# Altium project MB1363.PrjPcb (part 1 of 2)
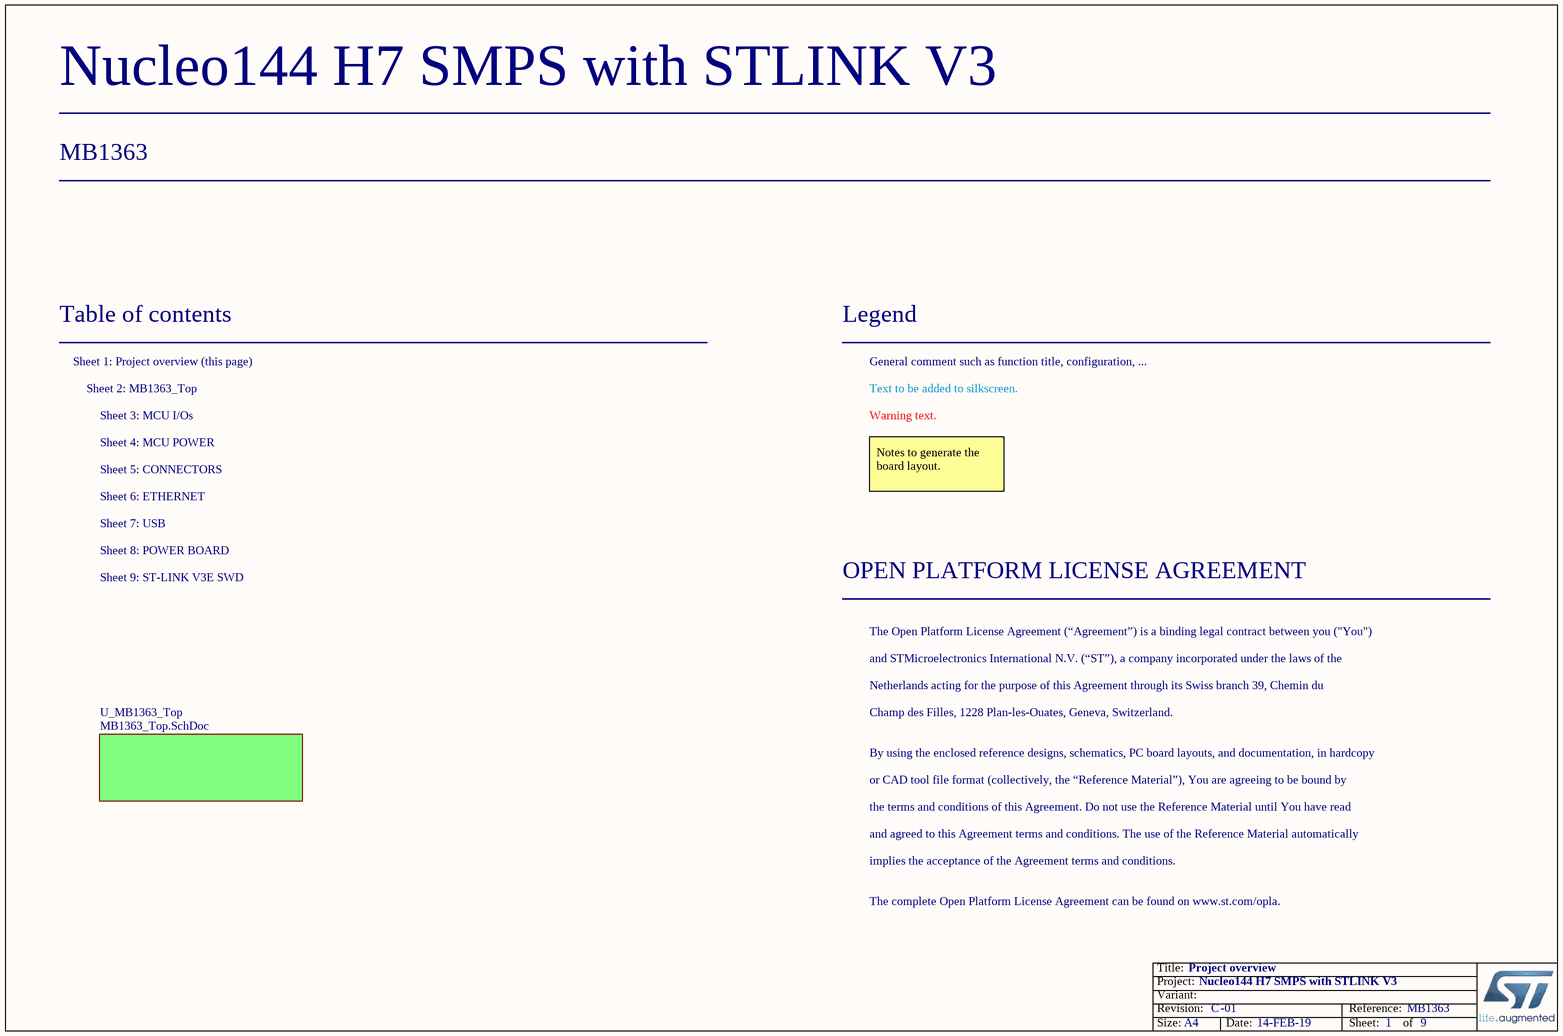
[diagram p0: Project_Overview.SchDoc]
Board_Reference: MB1363; Board_PCB_Revision: C; Board_Name: Nucleo144 H7 SMPS with STLINK V3; Board_Document_Date: 14-FEB-19; Board_Assembly_Revision: 01
9 sheets, 364 parts. Net scope: flat (ports and power ports of the same name join across sheets).
Board file: MB1363.PcbDoc
Sheets:
  Project_Overview.SchDoc
    U_MB1363_Top = mb1363_Top.SchDoc
      U_Connectors = Connectors.SchDoc
      U_Power_Board = Power_Board.SchDoc
      U_MCU_144_IOs = MCU_144_IOs.SchDoc
      U_MCU_144_POWER = MCU_144_POWER.SchDoc
      U_USB = USB.SchDoc
      U_Ethernet = Ethernet.SchDoc
      U_ST_LINK_V3E = ST_LINK_V3E.SchDoc

## Sheet Project_Overview.SchDoc: Project overview
size A4; Date: Not used; ApprovedBy: Not used; CheckedBy: Not used; Author: Not used; CompanyName: STMicroelectronics; DrawnBy: Not used; Engineer: Not used; Organization: Not used; Address1: Not used; Address2: Not used; Address3: Not used; Address4: Not used; DocumentNumber: 1; Revision: Not used; SheetNumber: 1; SheetTotal: 9

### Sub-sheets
U_MB1363_Top = MB1363_Top.SchDoc: no entries

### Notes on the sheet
- Table of contents
- Sheet 1: Project overview (this page)
- Legend
- General comment such as function title, configuration, ...
- Sheet 2: MB1363_Top
- Sheet 4: MCU POWER
- Sheet 3: MCU I/Os
- Text to be added to silkscreen.
- Warning text.
- Sheet 6: ETHERNET
- Sheet 5: CONNECTORS
- Notes to generate the board layout.
- Sheet 9: ST-LINK V3E SWD
- Sheet 7: USB
- Sheet 8: POWER BOARD
- OPEN PLATFORM LICENSE AGREEMENT
- The Open Platform License Agreement (“Agreement”) is a binding legal contract between you ("You")
- and STMicroelectronics International N.V. (“ST”), a company incorporated under the laws of the
- Netherlands acting for the purpose of this Agreement through its Swiss branch 39, Chemin du
- Champ des Filles, 1228 Plan-les-Ouates, Geneva, Switzerland.
- By using the enclosed reference designs, schematics, PC board layouts, and documentation, in hardcopy
- or CAD tool file format (collectively, the “Reference Material”), You are agreeing to be bound by
- the terms and conditions of this Agreement. Do not use the Reference Material until You have read
- and agreed to this Agreement terms and conditions. The use of the Reference Material automatically
- implies the acceptance of the Agreement terms and conditions.
- The complete Open Platform License Agreement can be found on www.st.com/opla.

## Sheet mb1363_Top.SchDoc: MB1363 Top: hierarchical view
size A4; Date: Not used; ApprovedBy: Not used; CheckedBy: Not used; Author: Not used; CompanyName: STMicroelectronics; DrawnBy: Not used; Engineer: Not used; Organization: Not used; Address1: Not used; Address2: Not used; Address3: Not used; Address4: Not used; DocumentNumber: 2; Revision: Not used; SheetNumber: 2; SheetTotal: 9
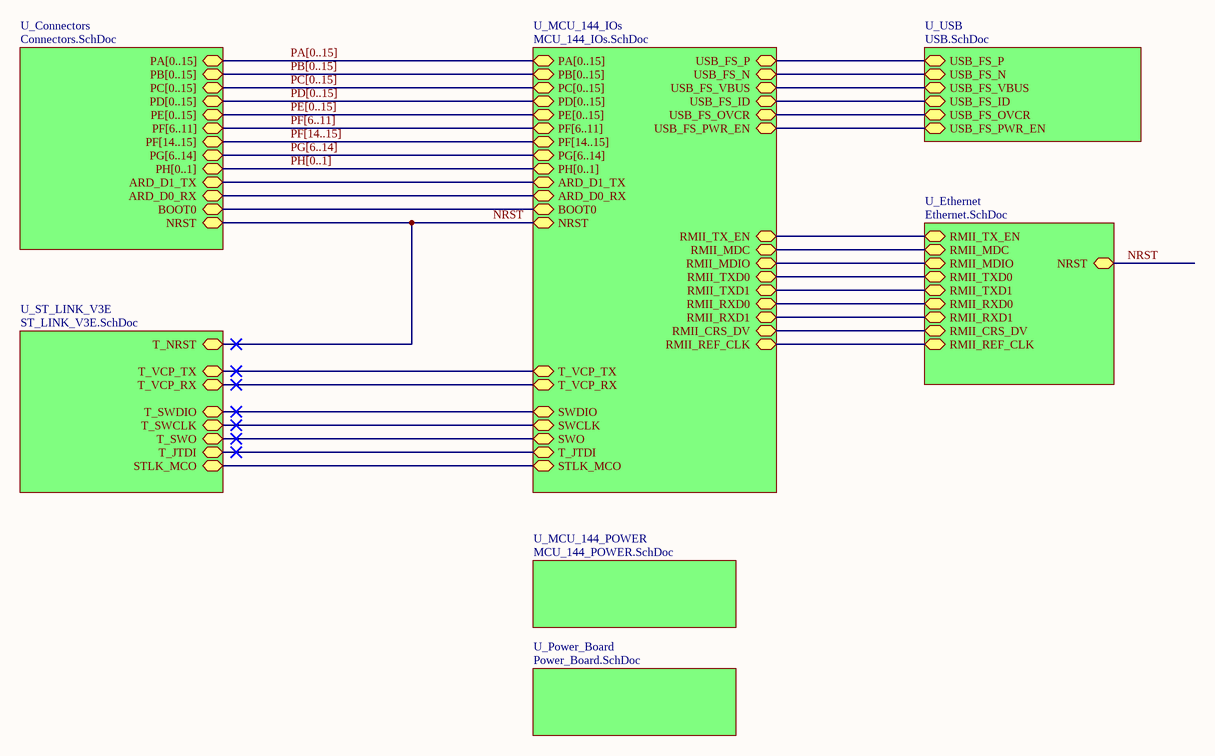
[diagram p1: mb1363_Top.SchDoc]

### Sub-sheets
U_Connectors = Connectors.SchDoc: PA[0..15] (bidir), PB[0..15] (bidir), PC[0..15] (bidir), NRST (bidir), PD[0..15] (bidir), PE[0..15] (bidir), PF[6..11] (bidir), PG[6..14] (bidir), PH[0..1] (bidir), BOOT0 (bidir), PF[14..15] (bidir), ARD_D1_TX (bidir), ARD_D0_RX (bidir)
U_Ethernet = Ethernet.SchDoc: RMII_CRS_DV (bidir), RMII_REF_CLK (bidir), RMII_TXD0 (bidir), RMII_RXD0 (bidir), RMII_TX_EN (bidir), NRST (bidir), RMII_RXD1 (bidir), RMII_MDC (bidir), RMII_TXD1 (bidir), RMII_MDIO (bidir)
U_MCU_144_IOs = MCU_144_IOs.SchDoc: NRST (bidir), BOOT0 (bidir), SWO (bidir), STLK_MCO (bidir), SWCLK (bidir), SWDIO (bidir), RMII_TX_EN (bidir), RMII_MDC (bidir), RMII_TXD0 (bidir), RMII_TXD1 (bidir), RMII_REF_CLK (bidir), RMII_RXD1 (bidir), RMII_MDIO (bidir), RMII_CRS_DV (bidir), RMII_RXD0 (bidir), USB_FS_N (bidir), USB_FS_P (bidir), USB_FS_OVCR (bidir), USB_FS_PWR_EN (bidir), USB_FS_VBUS (bidir), USB_FS_ID (bidir), T_VCP_TX (bidir), T_VCP_RX (bidir), PA[0..15] (bidir), PB[0..15] (bidir), PC[0..15] (bidir), PD[0..15] (bidir), PE[0..15] (bidir), PF[6..11] (bidir), PG[6..14] (bidir), PH[0..1] (bidir), PF[14..15] (bidir), ARD_D1_TX (bidir), ARD_D0_RX (bidir), T_JTDI (bidir)
U_MCU_144_POWER = MCU_144_POWER.SchDoc: no entries
U_Power_Board = Power_Board.SchDoc: no entries
U_ST_LINK_V3E = ST_LINK_V3E.SchDoc: T_NRST (bidir), STLK_MCO (bidir), T_SWDIO (bidir), T_VCP_TX (bidir), T_VCP_RX (bidir), T_SWCLK (bidir), T_SWO (bidir), T_JTDI (bidir)
U_USB = USB.SchDoc: USB_FS_N (bidir), USB_FS_P (bidir), USB_FS_OVCR (bidir), USB_FS_PWR_EN (bidir), USB_FS_VBUS (bidir), USB_FS_ID (bidir)

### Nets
NRST: sheet U_Connectors/NRST, sheet U_MCU_144_IOs/NRST, sheet U_Ethernet/NRST, sheet U_ST_LINK_V3E/T_NRST
(unnamed): sheet U_Connectors/BOOT0, sheet U_MCU_144_IOs/BOOT0
(unnamed): sheet U_Connectors/ARD_D1_TX, sheet U_MCU_144_IOs/ARD_D1_TX  [a separate net that carries the same name]
(unnamed): sheet U_Connectors/ARD_D0_RX, sheet U_MCU_144_IOs/ARD_D0_RX  [a separate net that carries the same name]
(unnamed): sheet U_MCU_144_IOs/SWO, sheet U_ST_LINK_V3E/T_SWO  [a separate net that carries the same name]
(unnamed): sheet U_MCU_144_IOs/STLK_MCO, sheet U_ST_LINK_V3E/STLK_MCO  [a separate net that carries the same name]
(unnamed): sheet U_MCU_144_IOs/SWCLK, sheet U_ST_LINK_V3E/T_SWCLK  [a separate net that carries the same name]
(unnamed): sheet U_MCU_144_IOs/SWDIO, sheet U_ST_LINK_V3E/T_SWDIO  [a separate net that carries the same name]
(unnamed): sheet U_MCU_144_IOs/RMII_TX_EN, sheet U_Ethernet/RMII_TX_EN  [a separate net that carries the same name]
(unnamed): sheet U_MCU_144_IOs/RMII_MDC, sheet U_Ethernet/RMII_MDC  [a separate net that carries the same name]
(unnamed): sheet U_MCU_144_IOs/RMII_TXD0, sheet U_Ethernet/RMII_TXD0  [a separate net that carries the same name]
(unnamed): sheet U_MCU_144_IOs/RMII_TXD1, sheet U_Ethernet/RMII_TXD1  [a separate net that carries the same name]
(unnamed): sheet U_MCU_144_IOs/RMII_REF_CLK, sheet U_Ethernet/RMII_REF_CLK  [a separate net that carries the same name]
(unnamed): sheet U_MCU_144_IOs/RMII_RXD1, sheet U_Ethernet/RMII_RXD1  [a separate net that carries the same name]
(unnamed): sheet U_MCU_144_IOs/RMII_MDIO, sheet U_Ethernet/RMII_MDIO  [a separate net that carries the same name]
(unnamed): sheet U_MCU_144_IOs/RMII_CRS_DV, sheet U_Ethernet/RMII_CRS_DV  [a separate net that carries the same name]
(unnamed): sheet U_MCU_144_IOs/RMII_RXD0, sheet U_Ethernet/RMII_RXD0  [a separate net that carries the same name]
(unnamed): sheet U_MCU_144_IOs/USB_FS_N, sheet U_USB/USB_FS_N  [a separate net that carries the same name]
(unnamed): sheet U_MCU_144_IOs/USB_FS_P, sheet U_USB/USB_FS_P  [a separate net that carries the same name]
(unnamed): sheet U_MCU_144_IOs/USB_FS_OVCR, sheet U_USB/USB_FS_OVCR  [a separate net that carries the same name]
(unnamed): sheet U_MCU_144_IOs/USB_FS_PWR_EN, sheet U_USB/USB_FS_PWR_EN  [a separate net that carries the same name]
(unnamed): sheet U_MCU_144_IOs/USB_FS_VBUS, sheet U_USB/USB_FS_VBUS  [a separate net that carries the same name]
(unnamed): sheet U_MCU_144_IOs/USB_FS_ID, sheet U_USB/USB_FS_ID  [a separate net that carries the same name]
(unnamed): sheet U_MCU_144_IOs/T_VCP_TX, sheet U_ST_LINK_V3E/T_VCP_TX  [a separate net that carries the same name]
(unnamed): sheet U_MCU_144_IOs/T_VCP_RX, sheet U_ST_LINK_V3E/T_VCP_RX  [a separate net that carries the same name]
(unnamed): sheet U_MCU_144_IOs/T_JTDI, sheet U_ST_LINK_V3E/T_JTDI  [a separate net that carries the same name]

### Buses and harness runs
bus PA[0..15] = sheet U_Connectors/PA[0..15] = sheet U_MCU_144_IOs/PA[0..15]
bus PB[0..15] = sheet U_Connectors/PB[0..15] = sheet U_MCU_144_IOs/PB[0..15]
bus PC[0..15] = sheet U_Connectors/PC[0..15] = sheet U_MCU_144_IOs/PC[0..15]
bus PD[0..15] = sheet U_Connectors/PD[0..15] = sheet U_MCU_144_IOs/PD[0..15]
bus PE[0..15] = sheet U_Connectors/PE[0..15] = sheet U_MCU_144_IOs/PE[0..15]
bus PF[6..11] = sheet U_Connectors/PF[6..11] = sheet U_MCU_144_IOs/PF[6..11]
bus PF[14..15] = sheet U_Connectors/PF[14..15] = sheet U_MCU_144_IOs/PF[14..15]
bus PG[6..14] = sheet U_Connectors/PG[6..14] = sheet U_MCU_144_IOs/PG[6..14]
bus PH[0..1] = sheet U_Connectors/PH[0..1] = sheet U_MCU_144_IOs/PH[0..1]

## Sheet Connectors.SchDoc: Connectors
size A3; Date: Not used; ApprovedBy: Not used; CheckedBy: Not used; Author: Not used; CompanyName: STMicroelectronics; DrawnBy: Not used; Engineer: Not used; Organization: Not used; Address1: Not used; Address2: Not used; Address3: Not used; Address4: Not used; DocumentNumber: 5; Revision: Not used; SheetNumber: 5; SheetTotal: 9
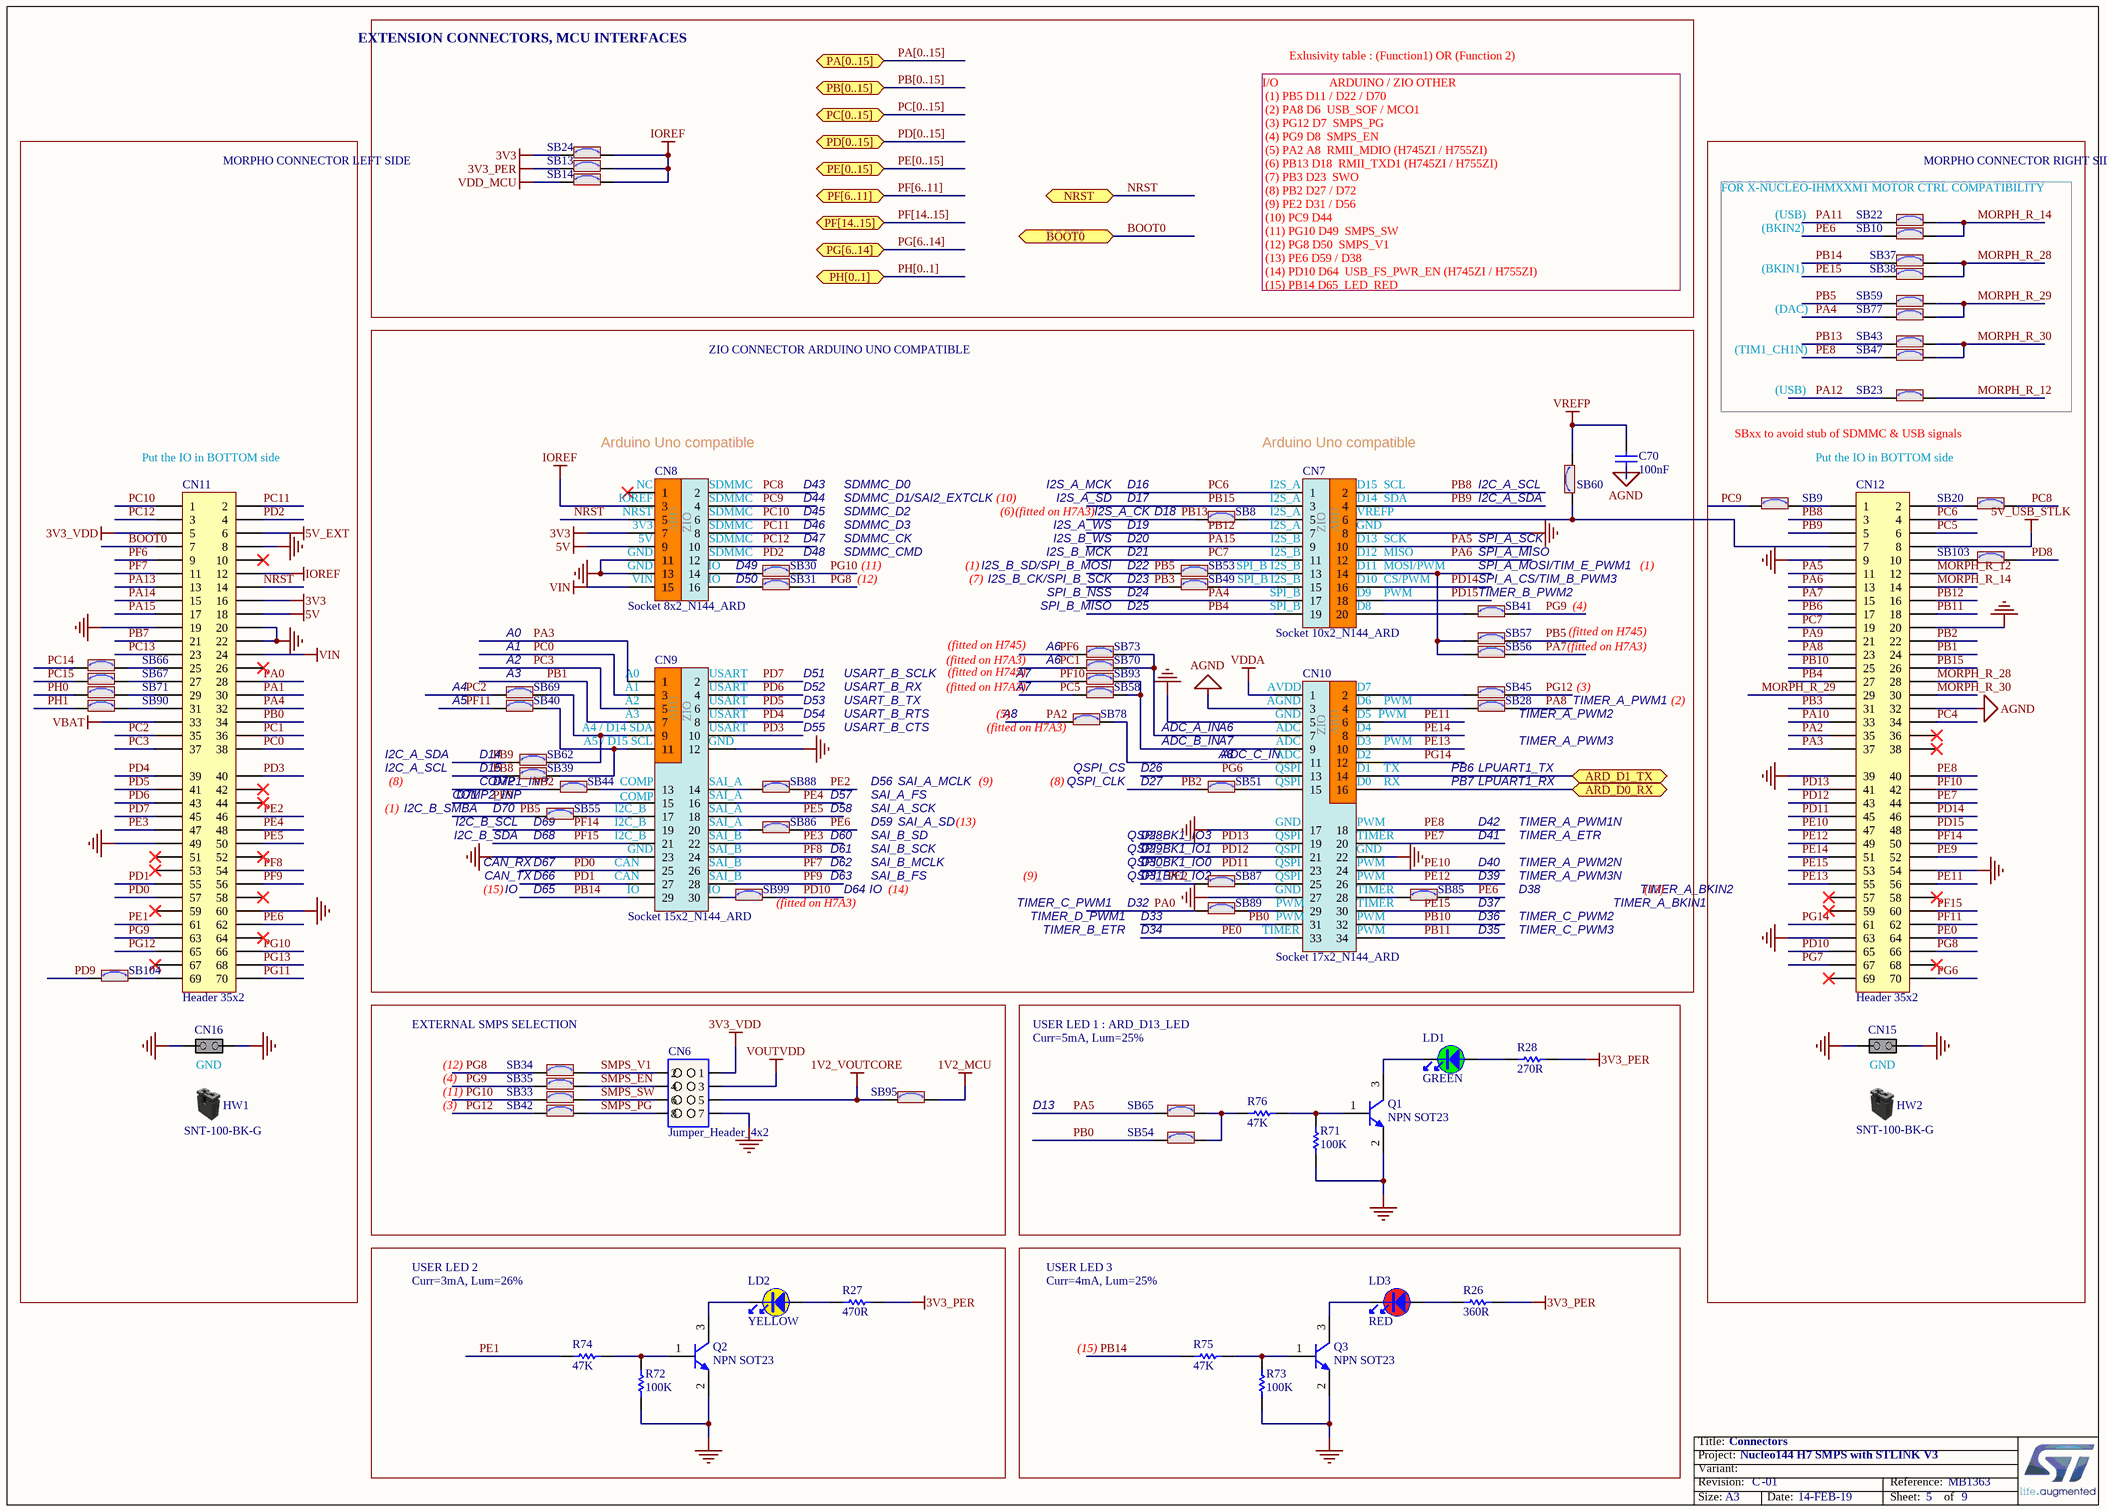
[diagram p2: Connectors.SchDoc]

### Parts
C70  value 100nF  [C0603]  (hidden comment: Capacitor)
CN6  value Jumper_Header_4x2  [CON_SAMTEC_TSW-104-07-X-D]  (hidden comment: Jumper_Header 4x2)
CN7  Socket 10x2_N144_ARD  [CON_SAMTEC_SSW-110-23-X-D_N144_ARD]
CN8  Socket 8x2_N144_ARD  [CON_SAMTEC_SSW-108-23-X-D_N144_ARD]
CN9  Socket 15x2_N144_ARD  [CON_SAMTEC_SSW-115-23-X-D_N144_ARD]
CN10  Socket 17x2_N144_ARD  [CON_SAMTEC_SSW-117-23-X-D_N144_ARD]
CN11  Header 35x2  [CON_SAMTEC_TSW-135-07-X-D]
CN12  Header 35x2  [CON_SAMTEC_TSW-135-07-X-D]
CN15  Jumper_Header 2x1  [CON_SAMTEC_TSW-102-09-X-S]  (value not drawn)
CN16  Jumper_Header 2x1  [CON_SAMTEC_TSW-102-09-X-S]  (value not drawn)
HW1  value SNT-100-BK-G  (hidden comment: Shunt Black 2.54mm)  (mechanical)
HW2  value SNT-100-BK-G  (hidden comment: Shunt Black 2.54mm)  (mechanical)
LD1  value GREEN  [LED_0603_OSRAM_LG-Q396-PS-35_GREEN_1A2K_H0P4]  (hidden comment: LED_green)
LD2  value YELLOW  [LED_0603_OSRAM_LY-Q396-P1Q2-36_YELLOW_1A2K_H0P4]  (hidden comment: LED_yellow)
LD3  value RED  [LED_0603_OSRAM_LS-Q976-NR-1_RED_1A2K_H0P8]  (hidden comment: LED_red)
Q1  value NPN SOT23  [NPN_SOT23]  (hidden comment: 9013-SOT23)
Q2  value NPN SOT23  [NPN_SOT23]  (hidden comment: 9013-SOT23)
Q3  value NPN SOT23  [NPN_SOT23]  (hidden comment: 9013-SOT23)
R26  value 360R  [R0603]  (hidden comment: Resistor)
R27  value 470R  [R0603]  (hidden comment: Resistor)
R28  value 270R  [R0402]  (hidden comment: Resistor)
R71  value 100K  [R0603]  (hidden comment: Resistor)
R72  value 100K  [R0603]  (hidden comment: Resistor)
R73  value 100K  [R0603]  (hidden comment: Resistor)
R74  value 47K  [R0603]  (hidden comment: Resistor)
R75  value 47K  [R0603]  (hidden comment: Resistor)
R76  value 47K  [R0603]  (hidden comment: Resistor)
SB8  SB_ON  [SOLDER-BRIDGE_R0603-0R]  (value not drawn)
SB9  SB_ON  [SOLDER-BRIDGE_R0603-0R]  (value not drawn)
SB10  SB_ON  [SOLDER-BRIDGE_R0603-0R]  (value not drawn)
SB13  SB_ON  [SOLDER-BRIDGE_R0402-0R]  (value not drawn)
SB14  SB_ON  [SOLDER-BRIDGE_R0402-0R]  (value not drawn)
SB20  SB_ON  [SOLDER-BRIDGE_R0603-0R]  (value not drawn)
SB22  SB_ON  [SOLDER-BRIDGE_R0603-0R]  (value not drawn)
SB23  SB_ON  [SOLDER-BRIDGE_R0603-0R]  (value not drawn)
SB24  SB_ON  [SOLDER-BRIDGE_R0402-0R]  (value not drawn)
SB28  SB_ON  [SOLDER-BRIDGE_R0603-0R]  (value not drawn)
SB30  SB_ON  [SOLDER-BRIDGE_R0603-0R]  (value not drawn)
SB31  SB_ON  [SOLDER-BRIDGE_R0603-0R]  (value not drawn)
SB33  SB_ON  [SOLDER-BRIDGE_R0603-0R]  (value not drawn)
SB34  SB_ON  [SOLDER-BRIDGE_R0603-0R]  (value not drawn)
SB35  SB_ON  [SOLDER-BRIDGE_R0603-0R]  (value not drawn)
SB37  SB_ON  [SOLDER-BRIDGE_R0402-0R]  (value not drawn)
SB38  SB_ON  [SOLDER-BRIDGE_R0402-0R]  (value not drawn)
SB39  SB_ON  [SOLDER-BRIDGE_R0603-0R]  (value not drawn)
SB40  SB_ON  [SOLDER-BRIDGE_R0603-0R]  (value not drawn)
SB41  SB_ON  [SOLDER-BRIDGE_R0603-0R]  (value not drawn)
SB42  SB_ON  [SOLDER-BRIDGE_R0603-0R]  (value not drawn)
SB43  SB_ON  [SOLDER-BRIDGE_R0603-0R]  (value not drawn)
SB44  SB_ON  [SOLDER-BRIDGE_R0603-0R]  (value not drawn)
SB45  SB_ON  [SOLDER-BRIDGE_R0603-0R]  (value not drawn)
SB47  SB_ON  [SOLDER-BRIDGE_R0603-0R]  (value not drawn)
SB49  SB_ON  [SOLDER-BRIDGE_R0603-0R]  (value not drawn)
SB51  SB_ON  [SOLDER-BRIDGE_R0603-0R]  (value not drawn)
SB53  SB_ON  [SOLDER-BRIDGE_R0603-0R]  (value not drawn)
SB54  SB_ON  [SOLDER-BRIDGE_R0603-0R]  (value not drawn)
SB55  SB_ON  [SOLDER-BRIDGE_R0603-0R]  (value not drawn)
SB56  SB_ON  [SOLDER-BRIDGE_R0603-0R]  (value not drawn)
SB57  SB_ON  [SOLDER-BRIDGE_R0603-0R]  (value not drawn)
SB58  SB_ON  [SOLDER-BRIDGE_R0603-0R]  (value not drawn)
SB59  SB_ON  [SOLDER-BRIDGE_R0603-0R]  (value not drawn)
SB60  SB_ON  [SOLDER-BRIDGE_R0603-0R]  (value not drawn)
SB62  SB_ON  [SOLDER-BRIDGE_R0603-0R]  (value not drawn)
SB65  SB_ON  [SOLDER-BRIDGE_R0603-0R]  (value not drawn)
SB66  SB_ON  [SOLDER-BRIDGE_R0603-0R]  (value not drawn)
SB67  SB_ON  [SOLDER-BRIDGE_R0603-0R]  (value not drawn)
SB69  SB_ON  [SOLDER-BRIDGE_R0603-0R]  (value not drawn)
SB70  SB_ON  [SOLDER-BRIDGE_R0603-0R]  (value not drawn)
SB71  SB_ON  [SOLDER-BRIDGE_R0603-0R]  (value not drawn)
SB73  SB_ON  [SOLDER-BRIDGE_R0603-0R]  (value not drawn)
SB77  SB_ON  [SOLDER-BRIDGE_R0603-0R]  (value not drawn)
SB78  SB_ON  [SOLDER-BRIDGE_R0603-0R]  (value not drawn)
SB85  SB_ON  [SOLDER-BRIDGE_R0603-0R]  (value not drawn)
SB86  SB_ON  [SOLDER-BRIDGE_R0603-0R]  (value not drawn)
SB87  SB_ON  [SOLDER-BRIDGE_R0603-0R]  (value not drawn)
SB88  SB_ON  [SOLDER-BRIDGE_R0603-0R]  (value not drawn)
SB89  SB_ON  [SOLDER-BRIDGE_R0603-0R]  (value not drawn)
SB90  SB_ON  [SOLDER-BRIDGE_R0603-0R]  (value not drawn)
SB93  SB_ON  [SOLDER-BRIDGE_R0603-0R]  (value not drawn)
SB95  SB_ON  [SOLDER-BRIDGE_R0603-0R]  (value not drawn)
SB99  SB_ON  [SOLDER-BRIDGE_R0603-0R]  (value not drawn)
SB103  SB_ON  [SOLDER-BRIDGE_R0603-0R]  (value not drawn)
SB104  SB_ON  [SOLDER-BRIDGE_R0603-0R]  (value not drawn)

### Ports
ARD_D0_RX (bidir), ARD_D1_TX (bidir), BOOT0, NRST, PA[0..15] (bidir), PB[0..15] (bidir), PC[0..15] (bidir), PD[0..15] (bidir), PE[0..15] (bidir), PF[6..11] (bidir), PF[14..15] (bidir), PG[6..14] (bidir), PH[0..1] (bidir)

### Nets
1V2_MCU: SB95.2
1V2_VOUTCORE: CN6.5 SB95.1
3V3: CN8.7 CN11.16 SB24.1
3V3_PER: R26.2 R27.2 R28.2 SB13.1
3V3_VDD: CN6.1 CN11.5
5V: CN8.9 CN11.18
5V_EXT: CN11.6
5V_USB_STLK: CN12.8
AGND: C70.1 CN10.3 CN12.32
GND: CN6.7 CN7.8 CN8.11 CN8.13 CN9.12 CN9.23 CN10.5 CN10.17 CN10.22 CN10.27 CN11.8 CN11.19 CN11.20 CN11.22 CN11.49 CN11.60 CN12.9 CN12.20 CN12.39 CN12.54 CN12.63 CN15.1(COMMON) CN15.2(NO) CN16.1(COMMON) CN16.2(NO) Q1.2(E) Q2.2(E) Q3.2(E) R71.1 R72.1 R73.1
IOREF: CN8.3 CN11.12 SB13.2 SB14.2 SB24.2
VBAT: CN11.33
VDD_MCU: SB14.1
VDDA: CN10.1
VIN: CN8.15 CN11.24
VOUTVDD: CN6.3
VREFP: C70.2 SB60.2
ARD_D0_RX: CN10.16 ; port ARD_D0_RX
ARD_D1_TX: CN10.14 ; port ARD_D1_TX
BOOT0: CN11.7 ; port BOOT0
MORPH_R_12: CN12.12 SB23.2
MORPH_R_14: CN12.14 SB10.2 SB22.2
MORPH_R_28: CN12.28 SB37.2 SB38.2
MORPH_R_29: CN12.29 SB59.2 SB77.2
MORPH_R_30: CN12.30 SB43.2 SB47.2
NRST: CN8.5 CN11.14 ; port NRST
PA0: CN11.28 SB89.1
PA1: CN11.30
PA2: CN12.35 SB78.1
PA3: CN9.1 CN12.37
PA4: CN7.17 CN11.32 SB77.1
PA5: CN7.10 CN12.11 SB65.1
PA6: CN7.12 CN12.13
PA7: CN12.15 SB56.2
PA8: CN12.23 SB28.2
PA9: CN12.21
PA10: CN12.33
PA11: SB22.1
PA12: SB23.1
PA13: CN11.13
PA14: CN11.15
PA15: CN7.9 CN11.17
PB0: CN10.31 CN11.34 SB54.1
PB1: CN9.7 CN12.24
PB2: CN12.22 SB44.1 SB51.1
PB3: CN12.31 SB49.1
PB4: CN7.19 CN12.27
PB5: SB53.1 SB55.1 SB57.2 SB59.1
PB6: CN12.17
PB7: CN11.21
PB8: CN7.2 CN12.3 SB39.1
PB9: CN7.4 CN12.5 SB62.1
PB10: CN10.32 CN12.25
PB11: CN10.34 CN12.18
PB12: CN7.7 CN12.16
PB13: SB8.1 SB43.1
PB14: CN9.29 R75.1 SB37.1
PB15: CN7.3 CN12.26
PC0: CN9.3 CN11.38
PC1: CN11.36 SB70.1
PC2: CN11.35 SB69.1
PC3: CN9.5 CN11.37
PC4: CN12.34
PC5: CN12.6 SB58.1
PC6: CN7.1 CN12.4
PC7: CN7.11 CN12.19
PC8: CN8.2 SB20.2
PC9: CN8.4 SB9.1
PC10: CN8.6 CN11.1
PC11: CN8.8 CN11.2
PC12: CN8.10 CN11.3
PC13: CN11.23
PC14: SB66.1
PC15: SB67.1
PD0: CN9.25 CN11.57
PD1: CN9.27 CN11.55
PD2: CN8.12 CN11.4
PD3: CN9.10 CN11.40
PD4: CN9.8 CN11.39
PD5: CN9.6 CN11.41
PD6: CN9.4 CN11.43
PD7: CN9.2 CN11.45
PD8: SB103.2
PD9: SB104.1
PD10: CN12.65 SB99.2
PD11: CN10.23 CN12.45
PD12: CN10.21 CN12.43
PD13: CN10.19 CN12.41
PD14: CN7.16 CN12.46
PD15: CN7.18 CN12.48
PE0: CN10.33 CN12.64
PE1: CN11.61 R74.1
PE2: CN11.46 SB87.1 SB88.2
PE3: CN9.22 CN11.47
PE4: CN9.16 CN11.48
PE5: CN9.18 CN11.50
PE6: CN11.62 SB10.1 SB85.2 SB86.2
PE7: CN10.20 CN12.44
PE8: CN10.18 CN12.40 SB47.1
PE9: CN9.15 CN12.52
PE10: CN10.24 CN12.47
PE11: CN10.6 CN12.56
PE12: CN10.26 CN12.49
PE13: CN10.10 CN12.55
PE14: CN10.8 CN12.51
PE15: CN10.30 CN12.53 SB38.1
PF6: CN11.9 SB73.1
PF7: CN9.26 CN11.11
PF8: CN9.24 CN11.54
PF9: CN9.28 CN11.56
PF10: CN12.42 SB93.1
PF11: CN12.62 SB40.1
PF14: CN9.19 CN12.50
PF15: CN9.21 CN12.60
PG6: CN10.13 CN12.70
PG7: CN12.67
PG8: CN12.66 SB31.2 SB34.2
PG9: CN11.63 SB35.2 SB41.2
PG10: CN11.66 SB30.2 SB33.2
PG11: CN11.70
PG12: CN11.65 SB42.2 SB45.2
PG13: CN11.68
PG14: CN10.12 CN12.61
PH0: SB71.1
PH1: SB90.1
SMPS_EN: CN6.4 SB35.1
SMPS_PG: CN6.8 SB42.1
SMPS_SW: CN6.6 SB33.1
SMPS_V1: CN6.2 SB34.1
NetCN7_5: CN7.5 SB8.2
NetCN7_6: CN7.6 CN12.7 SB60.1
NetCN7_13: CN7.13 SB53.2
NetCN7_14: CN7.14 SB56.1 SB57.1
NetCN7_15: CN7.15 SB49.2
NetCN7_20: CN7.20 SB41.1
NetCN8_14: CN8.14 SB30.1
NetCN8_16: CN8.16 SB31.1
NetCN9_9: CN9.9 SB62.2 SB69.2
NetCN9_11: CN9.11 SB39.2 SB40.2
NetCN9_13: CN9.13 SB44.2
NetCN9_14: CN9.14 SB88.1
NetCN9_17: CN9.17 SB55.2
NetCN9_20: CN9.20 SB86.1
NetCN9_30: CN9.30 SB99.1
NetCN10_2: CN10.2 SB45.1
NetCN10_4: CN10.4 SB28.1
NetCN10_7: CN10.7 SB70.2 SB73.2
NetCN10_9: CN10.9 SB58.2 SB93.2
NetCN10_11: CN10.11 SB78.2
NetCN10_15: CN10.15 SB51.2
NetCN10_25: CN10.25 SB87.2
NetCN10_28: CN10.28 SB85.1
NetCN10_29: CN10.29 SB89.2
NetCN11_25: CN11.25 SB66.2
NetCN11_27: CN11.27 SB67.2
NetCN11_29: CN11.29 SB71.2
NetCN11_31: CN11.31 SB90.2
NetCN11_69: CN11.69 SB104.2
NetCN12_1: CN12.1 SB9.2
NetCN12_2: CN12.2 SB20.1
NetCN12_10: CN12.10 SB103.1
NetLD1_1: LD1.1 R28.1
NetLD1_2: LD1.2 Q1.3(C)
NetLD2_1: LD2.1 R27.1
NetLD2_2: LD2.2 Q2.3(C)
NetLD3_1: LD3.1 R26.1
NetLD3_2: LD3.2 Q3.3(C)
NetQ1_1: Q1.1(B) R71.2 R76.2
NetQ2_1: Q2.1(B) R72.2 R74.2
NetQ3_1: Q3.1(B) R73.2 R75.2
NetR76_1: R76.1 SB54.2 SB65.2

Not connected (* = marked no-connect by the designer): CN8 1*; CN11 10* 26* 42* 44* 51* 52* 53* 58* 59* 64* 67*; CN12 36* 38* 57* 58* 59* 68* 69*

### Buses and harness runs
bus PA[0..15] = port PA[0..15]
bus PB[0..15] = port PB[0..15]
bus PC[0..15] = port PC[0..15]
bus PD[0..15] = port PD[0..15]
bus PE[0..15] = port PE[0..15]
bus PF[6..11] = port PF[6..11]
bus PF[14..15] = port PF[14..15]
bus PG[6..14] = port PG[6..14]
bus PH[0..1] = port PH[0..1]

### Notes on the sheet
- EXTENSION CONNECTORS, MCU INTERFACES
- Exlusivity table : (Function1) OR (Function 2)
- MORPHO CONNECTOR LEFT SIDE
- MORPHO CONNECTOR RIGHT SIDE
- FOR X-NUCLEO-IHMXXM1 MOTOR CTRL COMPATIBILITY
- (BKIN2)
- (USB)
- I/O	                ARDUINO / ZIO	OTHER
  (1)	PB5	D11 / D22 / D70
  (2)	PA8	D6		USB_SOF / MCO1
  (3)	PG12	D7		SMPS_PG
  (4)	PG9	D8		SMPS_EN
  (5)	PA2	A8		RMII_MDIO (H745ZI / H755ZI)
  (6)	PB13	D18		RMII_TXD1 (H745ZI / H755ZI)
  (7)	PB3	D23		SWO
  (8)	PB2	D27 / D72
  (9)	PE2	D31 / D56
  (10)	PC9	D44
  (11)	PG10	D49		SMPS_SW
  (12)	PG8	D50		SMPS_V1
  (13)	PE6	D59 / D38
  (14)	PD10	D64		USB_FS_PWR_EN (H745ZI / H755ZI)
  (15)	PB14	D65		LED_RED
- (BKIN1)
- (DAC)
- ZIO CONNECTOR ARDUINO UNO COMPATIBLE
- (TIM1_CH1N)
- (near CN8) Arduino Uno compatible
- (near CN7) Arduino Uno compatible
- (near SB23) SBxx to avoid stub of SDMMC & USB signals
- (near CN11) Put the IO in BOTTOM side
- (near CN8) NC
- (near CN8) IOREF
- (near CN8) NRST
- (near CN8) SDMMC
- D43
- D44
- D45
- SDMMC_D0
- SDMMC_D1/SAI2_EXTCLK
- SDMMC_D2
- (10)
- (6)
- (fitted on H7A3)
- I2S_A_SD
- I2S_A_MCK
- D16
- D17
- I2S_A_CK
- D18
- (near CN7) I2S_A
- (near CN7) VREFP
- (near CN7) D14
- (near CN7) D15
- (near CN7) SCL
- (near CN7) SDA
- (near SB60) I2C_A_SCL
- (near SB60) I2C_A_SDA
- Put the IO in BOTTOM side
- (near CN8) 3V3
- (near CN8) 5V
- (near CN8) GND
- (near CN8) VIN
- (near CN8) IO
- D49
- D50
- D46
- D47
- D48
- SDMMC_CK
- SDMMC_CMD
- SDMMC_D3
- (12)
- (11)
- (1)
- (7)
- I2S_A_WS
- I2S_B_SD/SPI_B_MOSI
- I2S_B_CK/SPI_B_SCK
- I2S_B_WS
- I2S_B_MCK
- D19
- D20
- D21
- D22
- D23
- SPI_B
- (near CN7) I2S_B
- (near CN7) D10
- (near CN7) D11
- (near CN7) D12
- (near CN7) D13
- (near CN7) SCK
- (near CN7) GND
- (near CN7) MISO
- (near CN7) MOSI/PWM
- (near CN7) CS/PWM
- (near SB41) SPI_A_CS/TIM_B_PWM3
- (near SB41) SPI_A_MOSI/TIM_E_PWM1
- SPI_A_SCK
- SPI_A_MISO
- A0
- A1
- (fitted on H745)
- A6
- SPI_B_MISO
- SPI_B_NSS
- D24
- D25
- (near CN7) SPI_B
- (near CN7) D8
- (near CN7) D9
- (near CN7) PWM
- (near SB41) TIMER_B_PWM2
- (4)
- A4
- A5
- A2
- (near SB69) A3
- (near CN9) A0
- (near CN9) A1
- (near CN9) A2
- (near CN9) A3
- (near CN9) USART
- D51
- D52
- D53
- D54
- USART_B_TX
- USART_B_RX
- USART_B_SCLK
- USART_B_RTS
- (5)
- A8
- A7
- (near CN10) GND
- (near CN10) AVDD
- (near CN10) AGND
- (near CN10) D7
- (near CN10) D6
- (near CN10) D5
- (near CN10) PWM
- TIMER_A_PWM2
- TIMER_A_PWM1
- (3)
- (2)
- I2C_A_SCL
- I2C_A_SDA
- (8)
- COMP1_INP
- D14
- D15
- D72
- (near CN9) COMP
- (near CN9) A4 / D14 SDA
- (near CN9) A5 / D15 SCL
- (near CN9) SAI_A
- (near CN9) GND
- D55
- USART_B_CTS
- D56
- SAI_A_MCLK
- (9)
- (near SB78) (fitted on H7A3)
- QSPI_CLK
- (near SB78) QSPI_CS
- D26
- D27
- ADC_A_IN
- (near SB51) ADC_B_IN
- (near SB51) ADC_C_IN
- (near SB51) A8
- (near CN10) ADC
- (near CN10) QSPI
- (near CN10) D2
- (near CN10) D4
- (near CN10) D3
- (near CN10) D1
- (near CN10) D0
- (near CN10) TX
- (near CN10) RX
- PB6
- PB7
- LPUART1_TX
- LPUART1_RX
- TIMER_A_PWM3
- COMP2_INP
- D71
- I2C_B_SMBA
- D70
- I2C_B_SCL
- (near SB55) I2C_B_SDA
- (near SB55) D69
- (near SB55) D68
- (near CN9) I2C_B
- (near CN9) SAI_B
- D57
- D58
- D60
- D61
- SAI_A_SCK
- SAI_A_FS
- SAI_B_SD
- SAI_B_SCK
- D59
- SAI_A_SD
- (13)
- QSPI_BK1_IO1
- QSPI_BK1_IO3
- D28
- D29
- (near CN10) TIMER
- D41
- D42
- TIMER_A_PWM1N
- TIMER_A_ETR
- (15)
- IO
- CAN_TX
- (near SB55) CAN_RX
- (near SB55) D67
- D66
- D65
- (near CN9) CAN
- (near CN9) IO
- (near SB99) (fitted on H7A3)
- D62
- D63
- D64
- SAI_B_FS
- SAI_B_MCLK
- (14)
- TIMER_C_PWM1
- TIMER_D_PWM1
- QSPI_BK1_IO0
- QSPI_BK1_IO2
- D32
- D30
- D31
- D33
- (near SB85) D36
- (near SB85) D37
- (near SB85) D39
- (near SB85) D40
- TIMER_A_PWM2N
- TIMER_A_PWM3N
- TIMER_C_PWM2
- D38
- TIMER_A_BKIN1
- TIMER_A_BKIN2
- TIMER_B_ETR
- D34
- (near SB85) D35
- TIMER_C_PWM3
- EXTERNAL SMPS SELECTION
- USER LED 1 : ARD_D13_LED
- Curr=5mA, Lum=25%
- GND
- D13
- USER LED 2
- Curr=3mA, Lum=26%
- USER LED 3
- Curr=4mA, Lum=25%

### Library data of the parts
C70 = MCD-00237: Capacitor, MLCC, 100nF, 6V3, X5R, 10%, 0603, T=0,8mm; Manufacturer_Part_Number: CC0603KRX5R5BB104; Manufacturer: YAGEO; Provided_By: SUBCO; ECCN_US: EAR99; ECCN_EU: NEC
CN6 = MCD-00633: Header, 4x2, 2,54mm, VR, TH, Height 5.84mm/2.54mm; Part_Type: Connector; Manufacturer_Part_Number: TSW-104-07-x-D; Manufacturer: SAMTEC; Provided_By: SUBCO
CN7 = MCD-01039: Socket, 10x2, 2.54mm, VR, TH, Height 8.51mm/10mm, Low insertion force.; Part_Type: Connector; Manufacturer_Part_Number: SSW-110-23-x-D; Manufacturer: SAMTEC; Provided_By: SUBCO
CN8 = MCD-01037: Socket, 8x2, 2.54mm, VR, TH, Height 8.51mm/10mm, Low insertion force.; Part_Type: Connector; Manufacturer_Part_Number: SSW-108-23-x-D; Manufacturer: SAMTEC; Provided_By: SUBCO
CN9 = MCD-01040: Socket, 15x2, 2.54mm, VR, TH, Height 8.51mm/10mm, Low insertion force.; Part_Type: Connector; Manufacturer_Part_Number: SSW-115-23-x-D; Manufacturer: SAMTEC; Provided_By: SUBCO
CN10 = MCD-01041: Socket, 17x2, 2.54mm, VR, TH, Height 8.51mm/10mm, Low insertion force; Part_Type: Connector; Manufacturer_Part_Number: SSW-117-23-x-D; Manufacturer: SAMTEC; Provided_By: SUBCO
CN11 CN12 = MCD-01210: Header, 35x2, 2,54mm, VR, TH, Height 5.84mm/2.54mm; Part_Type: Connector; Manufacturer_Part_Number: TSW-135-07-x-D; Manufacturer: SAMTEC; Provided_By: SUBCO
CN15 CN16 = MCD-00214: Header, 2x1, 2,54mm, VR, TH, Height 5.84mm/10.16mm; Manufacturer_Part_Number: TSW-102-09-x-S; Manufacturer: SAMTEC; Part_Type: Connector; Value: Header 2x1 16mm; Provided_By: SUBCO
HW1 HW2 = MCD-00043: SHUNT 2.54mm BLACK; Manufacturer: SAMTEC; Part_Type: Mechanical; Alternate_Manufacturer_Part_Number: 316102S111A; Alternate_Manufacturer: JIUBABA; Provided_By: SUBCO
LD1 = MCD-00588: LED Green, 0603 SMD, Forward Voltage Typ=2V, Max=2.5V; Part_Type: Display; Manufacturer_Part_Number: LG Q396-PS-35; Manufacturer: OSRAM OPTO SEMICONDUCTORS; Alternate_Manufacturer_Part_Number: VLMTG1300-GS08; Alternate_Manufacturer: VISHAY SEMICONDUCTOR OPTO DIVISION; Provided_By: SUBCO
LD2 = MCD-01061: LED Yellow, 0603 SMD, Forward Voltage min=1.7V, Typ=2V, Max=2.3V; Part_Type: Display; Manufacturer_Part_Number: LY Q396-P1Q2-36; Manufacturer: OSRAM OPTO SEMICONDUCTORS; Provided_By: SUBCO
LD3 = MCD-00586: LED Red, 0603 SMD, Forward Voltage Typ=2V, Max=2.5V; Part_Type: Display; Manufacturer_Part_Number: LS Q976-NR-1; Manufacturer: OSRAM OPTO SEMICONDUCTORS; Alternate_Manufacturer_Part_Number: VLMS1300-GS08; Alternate_Manufacturer: VISHAY SEMICONDUCTOR OPTO DIVISION; Provided_By: SUBCO
Q1-Q3 = MCD-00073: NPN Bipolar Transistor; Part_Type: IC; Manufacturer_Part_Number: BSR14; Manufacturer: ON SEMICONDUCTOR; Alternate_Manufacturer_Part_Number: MMBT2222LT1G / MMBT2222ALT1G / MMBT2222ALT3G; Provided_By: SUBCO; ECCN_US: EAR99; ECCN_EU: NEC
R26 = MCD-00462: Resistor,360R,0603,1%,1/10W; Manufacturer_Part_Number: RC0603FR-07360RL; Manufacturer: YAGEO; BMS_Part_Number: 9129744; Provided_By: SUBCO; ECCN_US: EAR99; ECCN_EU: NEC
R27 = MCD-00354: Resistor,470R,0603,1%,1/10W; Manufacturer_Part_Number: RC0603FR-07470RL; Manufacturer: YAGEO; BMS_Part_Number: 9129906; Provided_By: SUBCO; ECCN_US: EAR99; ECCN_EU: NEC
R28 = MCD-00441: Resistor,270R,0402,1%,1/16W; Manufacturer_Part_Number: RC0402FR-07270RL; Manufacturer: YAGEO; Provided_By: SUBCO; ECCN_US: EAR99; ECCN_EU: NEC
R71-R73 = MCD-00223: Resistor,100K,0603,1%,1/10W; Manufacturer_Part_Number: RC0603FR-07100KL; Manufacturer: YAGEO; Provided_By: SUBCO; ECCN_US: EAR99; ECCN_EU: NEC
R74-R76 = MCD-00222: Resistor,47K,0603,1%,1/10W; Manufacturer_Part_Number: RC0603FR-0747KL; Manufacturer: YAGEO; Provided_By: SUBCO; ECCN_US: EAR99; ECCN_EU: NEC
SB8-SB10 SB20 SB22 SB23 SB28 SB30 SB31 SB33-SB35 SB39-SB45 SB47 SB49 SB51 SB53-SB60 SB62 SB65-SB67 SB69-SB71 SB73 SB77 SB78 SB85-SB90 SB93 SB95 SB99 SB103 SB104 = MCD-00071: Solder Bridge ON; Part_Type: Mechanical; Manufacturer_Part_Number: RC0603JR-070RL; Manufacturer: YAGEO; Provided_By: SUBCO
SB13 SB14 SB24 SB37 SB38 = MCD-01618: Solder Bridge 0402 ON; Part_Type: Mechanical; Manufacturer_Part_Number: RC0402JR-070RL; Manufacturer: YAGEO; Provided_By: SUBCO

## Sheet Power_Board.SchDoc: MAIN POWER 5V / 3V3 / 1V8
size A4; Date: Not used; ApprovedBy: Not used; CheckedBy: Not used; Author: Not used; CompanyName: STMicroelectronics; DrawnBy: Not used; Engineer: Not used; Organization: Not used; Address1: Not used; Address2: Not used; Address3: Not used; Address4: Not used; DocumentNumber: 9; Revision: Not used; SheetNumber: 8; SheetTotal: 9
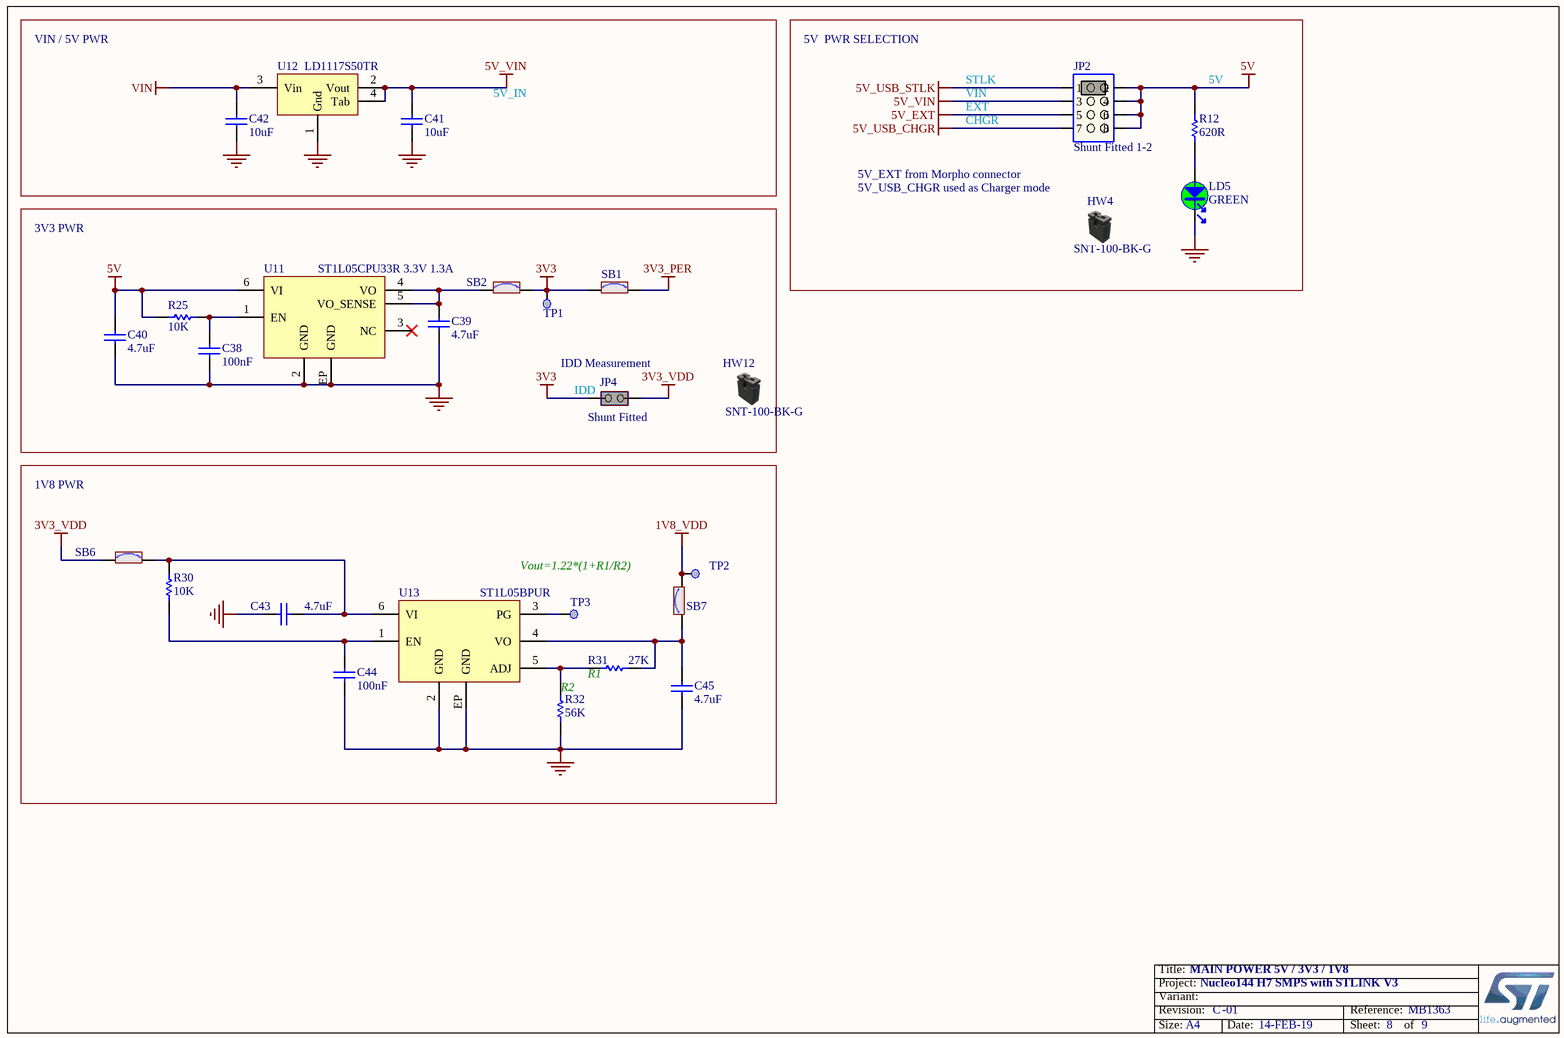
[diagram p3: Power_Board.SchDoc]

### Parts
C38  value 100nF  [C0402]  (hidden comment: Capacitor)
C39  value 4.7uF  [C0603]  (hidden comment: Capacitor)
C40  value 4.7uF  [C0603]  (hidden comment: Capacitor)
C41  value 10uF  [C0805]  (hidden comment: Capacitor)
C42  value 10uF  [C0805]  (hidden comment: Capacitor)
C43  value 4.7uF  [C0603]  (hidden comment: Capacitor)
C44  value 100nF  [C0402]  (hidden comment: Capacitor)
C45  value 4.7uF  [C0603]  (hidden comment: Capacitor)
HW4  value SNT-100-BK-G  (hidden comment: Shunt Black 2.54mm)  (mechanical)
HW12  value SNT-100-BK-G  (hidden comment: Shunt Black 2.54mm)  (mechanical)
JP2  value Shunt Fitted 1-2  [CON_SAMTEC_TSW-104-07-X-D]  (hidden comment: Jumper_Header 4x2 Fitted 1-2)
JP4  value Shunt Fitted  [CON_SAMTEC_TSW-102-07-G-S]  (hidden comment: Jumper_Header 2x1 Fitted)
LD5  value GREEN  [LED_0603_OSRAM_LG-Q396-PS-35_GREEN_1A2K_H0P4]  (hidden comment: LED_green)
R12  value 620R  [R0603]  (hidden comment: Resistor)
R25  value 10K  [R0402]  (hidden comment: Resistor)
R30  value 10K  [R0402]  (hidden comment: Resistor)
R31  value 27K  [R0402]  (hidden comment: Resistor)
R32  value 56K  [R0402]  (hidden comment: Resistor)
SB1  SB_ON  [SOLDER-BRIDGE_R0603-0R]  (value not drawn)
SB2  SB_ON  [SOLDER-BRIDGE_R0603-0R]  (value not drawn)
SB6  SB_ON  [SOLDER-BRIDGE_R0603-0R]  (value not drawn)
SB7  SB_ON  [SOLDER-BRIDGE_R0603-0R]  (value not drawn)
TP1  Test Point  [TP_SMD_1MM]  (value not drawn)  (no BOM)
TP2  Test Point  [TP_SMD_1MM]  (value not drawn)  (no BOM)
TP3  Test Point  [TP_SMD_1MM]  (value not drawn)  (no BOM)
U11  value ST1L05CPU33R 3.3V 1.3A  [ICC_DFN6-EPAD_3X3_P095]  (hidden comment: ST1L05CPU33R)
U12  LD1117S50TR  [REG_SOT223-TAB]
U13  ST1L05BPUR  [ICC_DFN6-EPAD_3X3_P095]

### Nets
1V8_VDD: SB7.2 TP2.1
3V3: JP4.1(COMMON) SB1.1 SB2.2 TP1.1
3V3_PER: SB1.2
3V3_VDD: JP4.2(NO) SB6.1
5V: C40.2 JP2.2 JP2.4 JP2.6 JP2.8 R12.2 R25.2 U11.6(VI)
5V_EXT: JP2.5
5V_USB_CHGR: JP2.7
5V_USB_STLK: JP2.1
5V_VIN: C41.2 JP2.3 U12.2(Vout) U12.4(Tab)
GND: C38.2 C39.1 C40.1 C41.1 C42.1 C43.2 C44.2 C45.1 LD5.2 R32.1 U11.2(GND) U11.EP(GND) U12.1(Gnd) U13.2(GND) U13.EP(GND)
VIN: C42.2 U12.3(Vin)
NetC38_1: C38.1 R25.1 U11.1(EN)
NetC39_2: C39.2 SB2.1 U11.4(VO) U11.5(VO_SENSE)
NetC43_1: C43.1 R30.1 SB6.2 U13.6(VI)
NetC44_1: C44.1 R30.2 U13.1(EN)
NetC45_2: C45.2 R31.1 SB7.1 U13.4(VO)
NetLD5_1: LD5.1 R12.1
NetR31_2: R31.2 R32.2 U13.5(ADJ)
NetTP3_1: TP3.1 U13.3(PG)

Not connected (* = marked no-connect by the designer): U11 3(NC)*

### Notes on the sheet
- VIN / 5V PWR
- 5V  PWR SELECTION
- 5V_IN
- STLK
- VIN
- EXT
- (near R12) 5V
- 5V_EXT from Morpho connector
- CHGR
- 3V3 PWR
- 5V_USB_CHGR used as Charger mode
- (near JP4) IDD Measurement
- (near JP4) IDD
- 1V8 PWR
- Vout=1.22*(1+R1/R2)
- (near R32) R2
- (near R31) R1

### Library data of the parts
C38 C44 = MCD-00006: Capacitor, MLCC, 100nF, 16V, X7R, 10%, 0402, T=0.5mm; Manufacturer_Part_Number: CC0402KRX7R7BB104; Manufacturer: YAGEO; Alternate_Manufacturer_Part_Number: GCM155R71C104KA55D; Alternate_Manufacturer: MURATA; Provided_By: SUBCO; ECCN_US: EAR99; ECCN_EU: NEC
C39 C43 C45 = MCD-01121: Capacitor, MLCC, 4.7µF, 10V, X5R, 20%, 0603, T=0,8mm; Manufacturer_Part_Number: GRM188R61A475ME15; Manufacturer: MURATA; Provided_By: SUBCO; ECCN_US: EAR99; ECCN_EU: NEC
C40 = MCD-00097: Capacitor, MLCC, 4.7uF, 16V, X5R, 20%, 0603, T=0,8mm; Manufacturer_Part_Number: GRM188R61C475KE11; Manufacturer: MURATA; Alternate_Manufacturer_Part_Number: GRM188R61C475MAAJ; Provided_By: SUBCO; ECCN_US: EAR99; ECCN_EU: NEC
C41 C42 = MCD-00014: Capacitor, MLCC, 10uF, 25V, X5R, 10%, 0805, T=0,85mm; Manufacturer_Part_Number: CC0805KRX5R8BB106; Manufacturer: YAGEO; Provided_By: SUBCO; ECCN_US: EAR99; ECCN_EU: NEC
HW4 HW12 = MCD-00043: as HW1 on sheet Connectors
JP2 = MCD-00686: Header, 4x2, 2,54mm, VR, TH, Height 5.84mm/2.54mm - Shunt Fitted 1-2; Part_Type: Connector; Manufacturer_Part_Number: TSW-104-07-x-D; Manufacturer: SAMTEC; Provided_By: SUBCO
JP4 = MCD-00683: Header, 2x1, 2,54mm, VR, TH, Height 5.84mm/2.54mm - Shunt Fitted by default; Part_Type: Connector; Manufacturer_Part_Number: TSW-102-07-x-S; Manufacturer: SAMTEC; Alternate_Manufacturer_Part_Number: 313102S111116; Alternate_Manufacturer: LIANYI; Provided_By: SUBCO
LD5 = MCD-00588: as LD1 on sheet Connectors
R12 = MCD-00500: Resistor,620R,0603,1%,1/10W; Manufacturer_Part_Number: RC0603FR-07620RL; Manufacturer: YAGEO; Provided_By: SUBCO; ECCN_US: EAR99; ECCN_EU: NEC
R25 R30 = MCD-00053: Resistor,10K,0402,1%,1/16W; Manufacturer_Part_Number: RC0402FR-0710KL; Manufacturer: YAGEO; Provided_By: SUBCO; ECCN_US: EAR99; ECCN_EU: NEC
R31 = MCD-00443: Resistor,27K,0402,1%,1/16W; Manufacturer_Part_Number: RC0402FR-0727KL; Manufacturer: YAGEO; Provided_By: SUBCO; ECCN_US: EAR99; ECCN_EU: NEC
R32 = MCD-00493: Resistor,56K,0402,1%,1/16W; Manufacturer_Part_Number: RC0402FR-0756KL; Manufacturer: YAGEO; Provided_By: SUBCO; ECCN_US: EAR99; ECCN_EU: NEC
SB1 SB2 SB6 SB7 = MCD-00071: as SB8 on sheet Connectors
TP1-TP3 = MCD-00074: Test Point 1mm; Part_Type: Mechanical
U11 = MCD-01025: LDO, 3.3V, 1.3A, Very low quiescent current BiCMOS voltage regulator; Part_Type: IC; Manufacturer: STMICROELECTRONICS; BMS_Part_Number: 9176246; Provided_By: SUBCO with ST control; ECCN_US: EAR99; ECCN_EU: NEC
U12 = MCD-00088: IC REG LDO 5V 0.8A SOT223; Manufacturer: STMICROELECTRONICS; BMS_Part_Number: 9176133; Provided_By: SUBCO with ST control; ECCN_US: EAR99; ECCN_EU: NEC
U13 = MCD-00581: LDO Linear Voltage Regulator IC Positive Adjustable 1 Output Adjustable 1.3A 6-DFN (3x3); Manufacturer: STMICROELECTRONICS; BMS_Part_Number: 9176239; Provided_By: SUBCO with ST control; ECCN_US: EAR99; ECCN_EU: NEC

## Sheet MCU_144_IOs.SchDoc: MCU 144 I/Os
size A4; Date: Not used; ApprovedBy: Not used; CheckedBy: Not used; Author: Not used; CompanyName: STMicroelectronics; DrawnBy: Not used; Engineer: Not used; Organization: Not used; Address1: Not used; Address2: Not used; Address3: Not used; Address4: Not used; DocumentNumber: 3; Revision: Not used; SheetNumber: 3; SheetTotal: 9
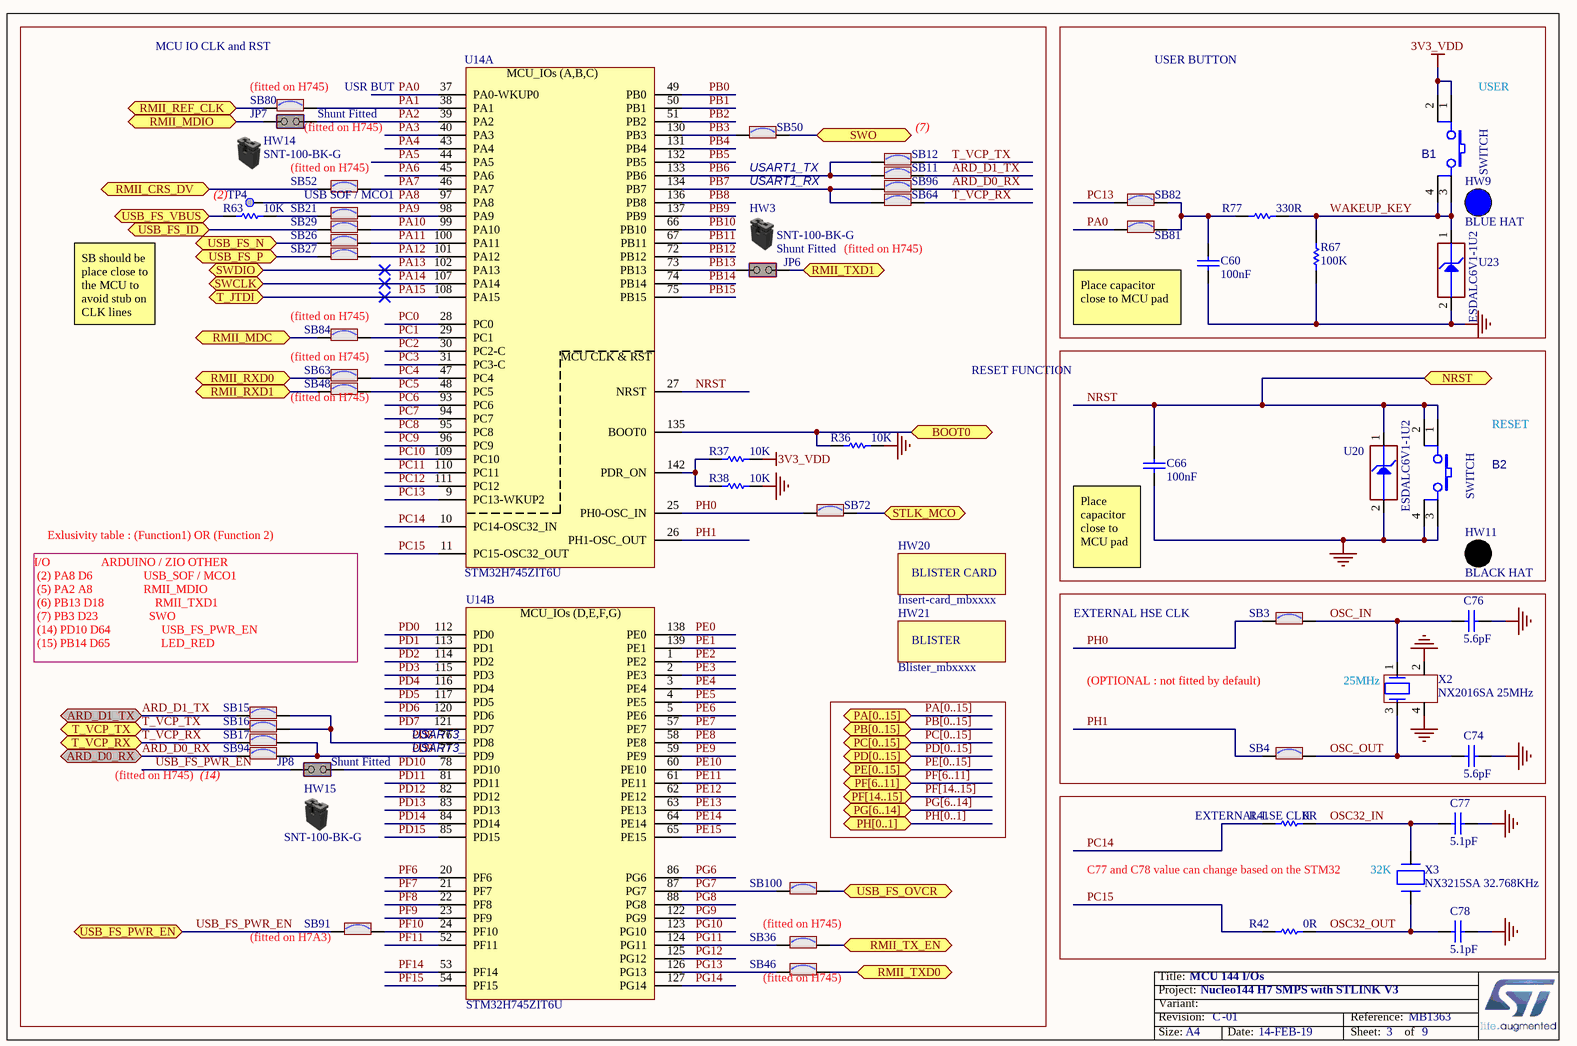
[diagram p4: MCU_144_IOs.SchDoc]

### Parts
B1  value SWITCH  [SWI_WEALTHMETAL_TD-0341_4P_BLUE]  (hidden comment: SW-PUSH-CMS)
B2  value SWITCH  [SWI_WEALTHMETAL_TD-0341_4P_BLACK]  (hidden comment: SW-PUSH-CMS)
C60  value 100nF  [C0603]  (hidden comment: Capacitor)
C66  value 100nF  [C0603]  (hidden comment: Capacitor)
C74  value 5.6pF  [C0402]  (hidden comment: Capacitor)
C76  value 5.6pF  [C0402]  (hidden comment: Capacitor)
C77  value 5.1pF  [C0603]  (hidden comment: Capacitor)
C78  value 5.1pF  [C0603]  (hidden comment: Capacitor)
HW3  value SNT-100-BK-G  (hidden comment: Shunt Black 2.54mm)  (mechanical)
HW9  value BLUE HAT  (hidden comment: BUTTON_HAT_BLUE)  (mechanical)
HW11  value BLACK HAT  (hidden comment: BUTTON_HAT_BLACK)  (mechanical)
HW14  value SNT-100-BK-G  (hidden comment: Shunt Black 2.54mm)  (mechanical)
HW15  value SNT-100-BK-G  (hidden comment: Shunt Black 2.54mm)  (mechanical)
HW20  value Insert-card_mbxxxx  (hidden comment: BLISTER CARD)  (mechanical)
HW21  value Blister_mbxxxx  (hidden comment: BLISTER)  (mechanical)
JP6  value Shunt Fitted  [CON_SAMTEC_TSW-102-07-G-S]  (hidden comment: Jumper_Header 2x1 Fitted)
JP7  value Shunt Fitted  [CON_SAMTEC_TSW-102-07-G-S]  (hidden comment: Jumper_Header 2x1 Fitted)
JP8  value Shunt Fitted  [CON_SAMTEC_TSW-102-07-G-S]  (hidden comment: Jumper_Header 2x1 Fitted)
R36  value 10K  [R0603]  (hidden comment: Resistor)
R37  value 10K  [R0603]  (hidden comment: Resistor)
R38  value 10K  [R0603]  (hidden comment: Resistor)
R41  value 0R  [R0603]  (hidden comment: Resistor)
R42  value 0R  [R0603]  (hidden comment: Resistor)
R63  value 10K  [R0402]  (hidden comment: Resistor)
R67  value 100K  [R0603]  (hidden comment: Resistor)
R77  value 330R  [R0603]  (hidden comment: Resistor)
SB3  SB_ON  [SOLDER-BRIDGE_R0603-0R]  (value not drawn)
SB4  SB_ON  [SOLDER-BRIDGE_R0603-0R]  (value not drawn)
SB11  SB_ON  [SOLDER-BRIDGE_R0603-0R]  (value not drawn)
SB12  SB_ON  [SOLDER-BRIDGE_R0603-0R]  (value not drawn)
SB15  SB_ON  [SOLDER-BRIDGE_R0603-0R]  (value not drawn)
SB16  SB_ON  [SOLDER-BRIDGE_R0603-0R]  (value not drawn)
SB17  SB_ON  [SOLDER-BRIDGE_R0603-0R]  (value not drawn)
SB21  SB_ON  [SOLDER-BRIDGE_R0603-0R]  (value not drawn)
SB26  SB_ON  [SOLDER-BRIDGE_R0603-0R]  (value not drawn)
SB27  SB_ON  [SOLDER-BRIDGE_R0603-0R]  (value not drawn)
SB29  SB_ON  [SOLDER-BRIDGE_R0603-0R]  (value not drawn)
SB36  SB_ON  [SOLDER-BRIDGE_R0603-0R]  (value not drawn)
SB46  SB_ON  [SOLDER-BRIDGE_R0603-0R]  (value not drawn)
SB48  SB_ON  [SOLDER-BRIDGE_R0603-0R]  (value not drawn)
SB50  SB_ON  [SOLDER-BRIDGE_R0603-0R]  (value not drawn)
SB52  SB_ON  [SOLDER-BRIDGE_R0603-0R]  (value not drawn)
SB63  SB_ON  [SOLDER-BRIDGE_R0603-0R]  (value not drawn)
SB64  SB_ON  [SOLDER-BRIDGE_R0603-0R]  (value not drawn)
SB72  SB_ON  [SOLDER-BRIDGE_R0603-0R]  (value not drawn)
SB80  SB_ON  [SOLDER-BRIDGE_R0603-0R]  (value not drawn)
SB81  SB_ON  [SOLDER-BRIDGE_R0603-0R]  (value not drawn)
SB82  SB_ON  [SOLDER-BRIDGE_R0603-0R]  (value not drawn)
SB84  SB_ON  [SOLDER-BRIDGE_R0603-0R]  (value not drawn)
SB91  SB_ON  [SOLDER-BRIDGE_R0603-0R]  (value not drawn)
SB94  SB_ON  [SOLDER-BRIDGE_R0603-0R]  (value not drawn)
SB96  SB_ON  [SOLDER-BRIDGE_R0603-0R]  (value not drawn)
SB100  SB_ON  [SOLDER-BRIDGE_R0603-0R]  (value not drawn)
TP4  Test Point  [TP_SMD_1MM]  (value not drawn)  (no BOM)
U14  value STM32H745ZIT6U  [ICC_LQFP144_20X20_P050_SOCKET_YAMAICHI_IC149-144-145-B5_NM]  (hidden comment: STM32H7_LQFP144_SMPS)  (parts A,B of 3)
U20  value ESDALC6V1-1U2  [ESD_ST0201]  (hidden comment: ESD-TRANSIL)
U23  value ESDALC6V1-1U2  [ESD_ST0201]  (hidden comment: ESD-TRANSIL)
X2  value NX2016SA 25MHz  [CRY_NX2016SA_4P]  (hidden comment: XTAL_4_PINS)
X3  value NX3215SA 32.768KHz  [CRY_NX3215SA_2P]  (hidden comment: XTAL_2_PINS)

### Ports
ARD_D0_RX (bidir), ARD_D1_TX (bidir), BOOT0 (bidir), NRST (bidir), PA[0..15] (bidir), PB[0..15] (bidir), PC[0..15] (bidir), PD[0..15] (bidir), PE[0..15] (bidir), PF[6..11] (bidir), PF[14..15] (bidir), PG[6..14] (bidir), PH[0..1] (bidir), RMII_CRS_DV (bidir), RMII_MDC (bidir), RMII_MDIO (bidir), RMII_REF_CLK (bidir), RMII_RXD0 (bidir), RMII_RXD1 (bidir), RMII_TX_EN (bidir), RMII_TXD0 (bidir), RMII_TXD1 (bidir), STLK_MCO (bidir), SWCLK (bidir), SWDIO (bidir), SWO (bidir), T_JTDI (bidir), T_VCP_RX (bidir), T_VCP_TX (bidir), USB_FS_ID (bidir), USB_FS_N (bidir), USB_FS_OVCR, USB_FS_P (bidir), USB_FS_PWR_EN, USB_FS_VBUS (bidir)

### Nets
3V3_VDD: B1.1 B1.2 R37.2
GND: B2.3 B2.4 C60.1 C66.1 C74.2 C76.2 C77.2 C78.2 R36.2 R38.2 R67.1 U20.2(GND) U23.2(GND) X2.2 X2.4
ARD_D0_RX: SB94.2 SB96.1 ; port ARD_D0_RX
ARD_D1_TX: SB11.1 SB15.2 ; port ARD_D1_TX
BOOT0: R36.1 U14.135(BOOT0) ; port BOOT0
NRST: B2.1 B2.2 C66.2 U14.27(NRST) U20.1(IO1) ; port NRST
OSC32_IN: C77.1 R41.2 X3.2(X2)
OSC32_OUT: C78.1 R42.2 X3.1(X1)
OSC_IN: C76.1 SB3.2 X2.1
OSC_OUT: C74.1 SB4.2 X2.3
PA0: SB81.2 U14.37(PA0-WKUP0)
PA1: SB80.1 U14.38(PA1)
PA2: JP7.2(NO) U14.39(PA2)
PA3: U14.40(PA3)
PA4: U14.43(PA4)
PA5: U14.44(PA5)
PA6: U14.45(PA6)
PA7: SB52.1 U14.46(PA7)
PA8: TP4.1 U14.97(PA8)
PA9: SB21.1 U14.98(PA9)
PA10: SB29.1 U14.99(PA10)
PA11: SB26.1 U14.100(PA11)
PA12: SB27.1 U14.101(PA12)
PA13: U14.102(PA13) ; port SWDIO
PA14: U14.107(PA14) ; port SWCLK
PA15: U14.108(PA15) ; port T_JTDI
PB0: U14.49(PB0)
PB1: U14.50(PB1)
PB2: U14.51(PB2)
PB3: SB50.2 U14.130(PB3)
PB4: U14.131(PB4)
PB5: U14.132(PB5)
PB6: SB11.2 SB12.2 U14.133(PB6)
PB7: SB64.2 SB96.2 U14.134(PB7)
PB8: U14.136(PB8)
PB9: U14.137(PB9)
PB10: U14.66(PB10)
PB11: U14.67(PB11)
PB12: U14.72(PB12)
PB13: JP6.1(COMMON) U14.73(PB13)
PB14: U14.74(PB14)
PB15: U14.75(PB15)
PC0: U14.28(PC0)
PC1: SB84.2 U14.29(PC1)
PC2: U14.30(PC2-C)
PC3: U14.31(PC3-C)
PC4: SB63.2 U14.47(PC4)
PC5: SB48.2 U14.48(PC5)
PC6: U14.93(PC6)
PC7: U14.94(PC7)
PC8: U14.95(PC8)
PC9: U14.96(PC9)
PC10: U14.109(PC10)
PC11: U14.110(PC11)
PC12: U14.111(PC12)
PC13: SB82.2 U14.9(PC13-WKUP2)
PC14: R41.1 U14.10(PC14-OSC32_IN)
PC15: R42.1 U14.11(PC15-OSC32_OUT)
PD0: U14.112(PD0)
PD1: U14.113(PD1)
PD2: U14.114(PD2)
PD3: U14.115(PD3)
PD4: U14.116(PD4)
PD5: U14.117(PD5)
PD6: U14.120(PD6)
PD7: U14.121(PD7)
PD8: SB15.1 SB16.1 U14.76(PD8)
PD9: SB17.1 SB94.1 U14.77(PD9)
PD10: JP8.2(NO) U14.78(PD10)
PD11: U14.81(PD11)
PD12: U14.82(PD12)
PD13: U14.83(PD13)
PD14: U14.84(PD14)
PD15: U14.85(PD15)
PE0: U14.138(PE0)
PE1: U14.139(PE1)
PE2: U14.1(PE2)
PE3: U14.2(PE3)
PE4: U14.3(PE4)
PE5: U14.4(PE5)
PE6: U14.5(PE6)
PE7: U14.57(PE7)
PE8: U14.58(PE8)
PE9: U14.59(PE9)
PE10: U14.60(PE10)
PE11: U14.61(PE11)
PE12: U14.62(PE12)
PE13: U14.63(PE13)
PE14: U14.64(PE14)
PE15: U14.65(PE15)
PF6: U14.20(PF6)
PF7: U14.21(PF7)
PF8: U14.22(PF8)
PF9: U14.23(PF9)
PF10: SB91.1 U14.24(PF10)
PF11: U14.52(PF11)
PF14: U14.53(PF14)
PF15: U14.54(PF15)
PG6: U14.86(PG6)
PG7: SB100.2 U14.87(PG7)
PG8: U14.88(PG8)
PG9: U14.122(PG9)
PG10: U14.123(PG10)
PG11: SB36.2 U14.124(PG11)
PG12: U14.125(PG12)
PG13: SB46.2 U14.126(PG13)
PG14: U14.127(PG14)
PH0: SB3.1 SB72.1 U14.25(PH0-OSC_IN)
PH1: SB4.1 U14.26(PH1-OSC_OUT)
RMII_CRS_DV: SB52.2 ; port RMII_CRS_DV
RMII_MDC: SB84.1 ; port RMII_MDC
RMII_MDIO: JP7.1(COMMON) ; port RMII_MDIO
RMII_REF_CLK: SB80.2 ; port RMII_REF_CLK
RMII_RXD0: SB63.1 ; port RMII_RXD0
RMII_RXD1: SB48.1 ; port RMII_RXD1
RMII_TX_EN: SB36.1 ; port RMII_TX_EN
RMII_TXD0: SB46.1 ; port RMII_TXD0
RMII_TXD1: JP6.2(NO) ; port RMII_TXD1
STLK_MCO: SB72.2 ; port STLK_MCO
SWO: SB50.1 ; port SWO
T_VCP_RX: SB17.2 SB64.1 ; port T_VCP_RX
T_VCP_TX: SB12.1 SB16.2 ; port T_VCP_TX
USB_FS_ID: SB29.2 ; port USB_FS_ID
USB_FS_N: SB26.2 ; port USB_FS_N
USB_FS_OVCR: SB100.1 ; port USB_FS_OVCR
USB_FS_P: SB27.2 ; port USB_FS_P
USB_FS_PWR_EN: JP8.1(COMMON) SB91.2 ; port USB_FS_PWR_EN
USB_FS_VBUS: R63.1 ; port USB_FS_VBUS
WAKEUP_KEY: B1.3 B1.4 R67.2 R77.2 U23.1(IO1)
NetC60_2: C60.2 R77.1 SB81.1 SB82.1
NetR37_1: R37.1 R38.1 U14.142(PDR_ON)
NetR63_2: R63.2 SB21.2

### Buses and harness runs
bus PA[0..15] = port PA[0..15]
bus PB[0..15] = port PB[0..15]
bus PC[0..15] = port PC[0..15]
bus PD[0..15] = port PD[0..15]
bus PE[0..15] = port PE[0..15]
bus PF[6..11] = port PF[6..11]
bus PF[14..15] = port PF[14..15]
bus PG[6..14] = port PG[6..14]
bus PH[0..1] = port PH[0..1]

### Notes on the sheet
- MCU IO CLK and RST
- (near SB80) (fitted on H745)
- USR BUT
- USER BUTTON
- (near B1) USER
- (near SB52) (fitted on H745)
- (fitted on H745)
- USART1_TX
- USART1_RX
- (7)
- (2)
- (near SB52) USB SOF / MCO1
- SB should be place close to the MCU to avoid stub on CLK lines
- (near SB84) (fitted on H745)
- Place capacitor close to MCU pad
- RESET FUNCTION
- (near SB48) (fitted on H745)
- RESET
- Exlusivity table : (Function1) OR (Function 2)
- (near C66) Place capacitor close to MCU pad
- I/O	                ARDUINO / ZIO	OTHER
  (2)	PA8	D6	                USB_SOF / MCO1
  (5)	PA2	A8	                RMII_MDIO
  (6)	PB13	D18	                RMII_TXD1
  (7)	PB3	D23	                SWO
  (14)	PD10	D64	                USB_FS_PWR_EN
  (15)	PB14	D65	                LED_RED
- EXTERNAL HSE CLK
- (OPTIONAL : not fitted by default)
- (near X2) 25MHz
- (14)
- USART3_TX
- USART3_RX
- EXTERNAL LSE CLK
- (near SB36) (fitted on H745)
- C77 and C78 value can change based on the STM32
- (near X3) 32K
- (near SB91) (fitted on H7A3)
- (near SB46) (fitted on H745)

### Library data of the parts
B1 = MCD-00002: Non-Open Push-Button 0.1A 24V; Manufacturer_Part_Number: TD-0341; Manufacturer: WEALTHMETAL; Part_Type: Misc; Provided_By: SUBCO
B2 = MCD-00001: Non-Open Push-Button 0.1A 24V BLACK; Manufacturer_Part_Number: TD-0341; Manufacturer: WEALTHMETAL; Part_Type: Misc; Provided_By: SUBCO
C60 C66 = MCD-00237: as C70 on sheet Connectors
C74 C76 = MCD-01374: Capacitor, MLCC, 5.6pF, 50V, NPO, 5%, 0402, T=0,5mm; Manufacturer_Part_Number: CC0402BRNPO9BN5R6; Manufacturer: YAGEO; Provided_By: SUBCO
C77 C78 = MCD-01367: Capacitor,5.1pF,0.25pF,50V,NPO,0603; Manufacturer_Part_Number: CC0603CRNPO9BN5R1; Manufacturer: YAGEO; Provided_By: SUBCO
HW3 HW14 HW15 = MCD-00043: as HW1 on sheet Connectors
HW9 = MCD-00634: Blue Hat for switch TD0341X-G01-BLU; Part_Type: Mechanical; Manufacturer_Part_Number: 988.16.09.3.00002_SH-517; Manufacturer: JIUBABA; Provided_By: SUBCO
HW11 = MCD-00635: Black Hat for switch TD0341X-G01-BLA; Part_Type: Mechanical; Manufacturer_Part_Number: 988.16.09.3.00003_SH-517; Manufacturer: JIUBABA; Provided_By: SUBCO
HW20 = MCD-00038: Part_Type: Mechanical; Provided_By: SUBCO
HW21 = MCD-00037: Part_Type: Mechanical; Provided_By: SUBCO
JP6-JP8 = MCD-00683: as JP4 on sheet Power_Board
R36-R38 = MCD-00220: Resistor,10K,0603,1%,1/10W; Manufacturer_Part_Number: RC0603FR-0710KL; Manufacturer: YAGEO; Provided_By: SUBCO; ECCN_US: EAR99; ECCN_EU: NEC
R41 R42 = MCD-00056: Resistor,0R,0603,5%,1/10W; Manufacturer_Part_Number: RC0603JR-070RL; Manufacturer: YAGEO; Provided_By: SUBCO; ECCN_US: EAR99; ECCN_EU: NEC
R63 = MCD-00053: as R25 on sheet Power_Board
R67 = MCD-00223: as R71 on sheet Connectors
R77 = MCD-00197: Resistor,330R,0603,1%,1/10W; Manufacturer_Part_Number: RC0603FR-07330RL; Manufacturer: YAGEO; BMS_Part_Number: 9129729; Provided_By: SUBCO; ECCN_US: EAR99; ECCN_EU: NEC
SB3 SB4 SB11 SB12 SB15-SB17 SB21 SB26 SB27 SB29 SB36 SB46 SB48 SB50 SB52 SB63 SB64 SB72 SB80-SB82 SB84 SB91 SB94 SB96 SB100 = MCD-00071: as SB8 on sheet Connectors
TP4 = MCD-00074: Test Point 1mm; Part_Type: Mechanical
U14 = MCD-01401: STM32H745ZIT6U, LQFP144 package, 20x20, with socket footprint; Part_Type: IC; Manufacturer: STMICROELECTRONICS; BMS_Part_Number: 9175297 (cut 2.0); ECCN_US: 3A991A2; ECCN_EU: NEC; Provided_By: SUBCO with ST control
U20 U23 = MCD-00170: ESD protection 6V1; Part_Type: Diode; Manufacturer: STMICROELECTRONICS; BMS_Part_Number: 9151132; Provided_By: SUBCO with ST control; ECCN_US: EAR99; ECCN_EU: NEC
X2 = MCD-01364: Crystal 25MHz, 6pF, +-20ppm, 80ohms max, SMD; Part_Type: Crystal_Osc; Manufacturer_Part_Number: NX2016SA 25MHz EXS00A-CS11321; Manufacturer: NDK; BMS_Part_Number: 9157044; Provided_By: SUBCO; ECCN_US: EAR99; ECCN_EU: NEC
X3 = MCD-00091: Crystal 32.768kHz, 6pF, +-20ppm, 50Kohms max, SMD; Manufacturer_Part_Number: NX3215SA 32.768KHz EXS00A-MU00525; Manufacturer: NDK; Part_Type: Crystal_Osc; BMS_Part_Number: 9157034; Provided_By: SUBCO; ECCN_US: EAR99; ECCN_EU: NEC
